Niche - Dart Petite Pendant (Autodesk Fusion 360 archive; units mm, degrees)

design "Dart Petite" references "PCB Single Pendant Canopy"
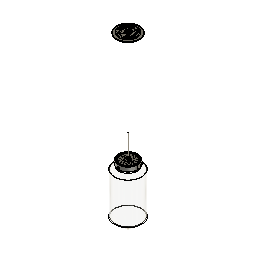
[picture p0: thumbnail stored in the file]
base_feature "Base Feature" bodies "Glass-Dart Petite"
external_derived "ExternalDerived1" bodies "Set Screw", "Strain Relief", "Lead-1", "Lead-2", "Lead-2.1", "Lead-1.1", "Coax", "Stem"
move "Move1"
move "Move2"
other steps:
derived_base_feature "Derived Base Feature" bodies "Set Screw", "Strain Relief", "Lead-1", "Lead-2", "Lead-2.1", "Lead-1.1", "Coax", "Stem"
create_component "CreateComponent1"
named bodies: "Glass-Dart Petite", "Set Screw", "Strain Relief", "Lead-1", "Lead-2", "Lead-2.1", "Lead-1.1", "Coax", "Stem", "Strain Relief Cap", "Nylon Gripper (2)", "Cap", "Thumbscrew (1)", "Thumbscrew (2)", "Thumbscrew (3)", "Niche-PCB", "FJ-Plug Cover", "FJ-Plug", "FJ-Plug1.1", "FJ-Plug1.2", "FJ-Plug1.3", "Fj-Plug1.4", "Canopy", "FJ-Port", "FJ-Port1.1", "Spacer", "Universal Mount", "FJ-Port Cover", "Diffuser"

design "FJ Plug - PCB-Hardware"
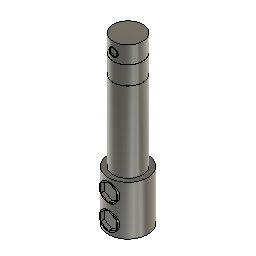
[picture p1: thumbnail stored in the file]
sketch "Sketch1" plane through (0, 0, 0) normal (0, 0, 1) x axis (1, 0, 0)
  circle C1 centre (0, 0) radius 3.048
  point P1 (0, 0)
  point P2 (0, 0)
  coincident P1 P2
  dimension "d1" diameter C1 = 6.096
extrude "Extrude1" new body sketch "Sketch1" along normal blind 34.036
sketch "Sketch2" plane through (0, 0, 0) normal (0, 0, 1) x axis (1, 0, 0)
  circle C1 centre (0, 0) radius 4.064
  point P1 (0, 0)
  point P2 (0, 0)
  coincident P1 P2
  dimension "d4" diameter C1 = 8.128
extrude "Extrude2" add sketch "Sketch2" along normal blind 10.16
sketch "Sketch3" plane through (0, 0, 0) normal (0, 1, 0) x axis (1, 0, 0)
  line L1 (6.35, 0) -> (-6.35, 0)
  line L2 (6.35, -30.48) -> (-6.35, -30.48)
  line L3 (2.54, -30.48) -> (6.35, -30.48)
  line L4 (2.54, -26.67) -> (2.54, -30.48)
  line L5 (6.35, -26.67) -> (2.54, -26.67)
  line L6 (6.35, -30.48) -> (6.35, -26.67)
  horizontal L1
  horizontal L3
  vertical L4
  horizontal L5
  vertical L6
  dimension "d7" = 30.48
revolve "Revolve1" sketch "Sketch3" AlongAngle 360
sketch "Sketch4" plane through (0, 0, 0) normal (0, 1, 0) x axis (1, 0, 0)
  line L1 (2.54, -30.48) -> (3.048, -30.48)
  line L2 (2.54, -26.67) -> (2.54, -30.48)
  line L3 (3.048, -26.67) -> (2.54, -26.67)
  line L4 (3.048, -30.48) -> (3.048, -26.67)
  horizontal L1
  vertical L2
  horizontal L3
  vertical L4
revolve "Revolve2" sketch "Sketch4" AlongAngle 360
chamfer "Chamfer1" distance 0.0254
chamfer "Chamfer2" distance 0.0254
hole "Hole1" HoleDepth 33.401 HoleDiameter 4.826 TipAngle 180
hole "Hole2" HoleDepth 3.81 HoleDiameter 1.778 TipAngle 180
hole "Hole3" HoleDepth 3.81 HoleDiameter 3.81 TipAngle 180
hole "Hole4" HoleDepth 3.81 HoleDiameter 3.81 TipAngle 180
sketch "Sketch5" plane through (0, 0, 0) normal (0, 1, 0) x axis (1, 0, 0)
  circle C1 centre (0, -32.0802) radius 0.889
  dimension "d24" diameter C1 = 1.778
extrude "Extrude3" new body sketch "Sketch5" along normal blind 1.778
move "Move1"
sketch "Sketch6" plane through (0, -3.048, 0) normal (0, -1, 0) x axis (1, 0, 0)
  line L1 (0.7259, 31.6611) -> (0, 31.242)
  line L2 (0.7259, 32.4993) -> (0.7259, 31.6611)
  line L3 (0, 32.9184) -> (0.7259, 32.4993)
  line L4 (-0.7259, 32.4993) -> (0, 32.9184)
  line L5 (-0.7259, 31.6611) -> (-0.7259, 32.4993)
  line L6 (0, 31.242) -> (-0.7259, 31.6611)
  circle C1 centre (0, 32.0802) radius 0.889
  point P2 (0, 32.0802)
  point P9 (0, 32.0802)
  coincident P2 P9
extrude "Extrude4" cut sketch "Sketch6" profile of L1 L2 L3 L4 L5 L6 against normal blind 0.254
sketch "Sketch7" plane through (0, 0, 0) normal (0, 1, 0) x axis (1, 0, 0)
  circle C1 centre (0, -2.4384) radius 1.905
  circle C2 centre (0, -7.5565) radius 1.905
  dimension "d29" diameter C1 = 3.81
  dimension "d30" diameter C2 = 3.81
extrude "Extrude5" new body sketch "Sketch7" profile of C2 along normal blind 3.81
move "Move2"
sketch "Sketch8" plane through (0, -4.064, 0) normal (0, -1, 0) x axis (1, 0, 0)
  line L1 (1.5948, 6.6357) -> (0, 5.715)
  line L2 (1.5948, 8.4772) -> (1.5948, 6.6357)
  line L3 (0, 9.398) -> (1.5948, 8.4772)
  line L4 (-1.5948, 8.4772) -> (0, 9.398)
  line L5 (-1.5948, 6.6357) -> (-1.5948, 8.4772)
  line L6 (0, 5.715) -> (-1.5948, 6.6357)
  circle C1 centre (0, 7.5565) radius 1.905
  point P2 (0, 7.5565)
  point P9 (0, 7.5565)
  coincident P2 P9
extrude "Extrude6" cut sketch "Sketch8" profile of L1 L2 L3 L4 L5 L6 against normal blind 0.762
copy_paste_bodies "CopyPasteBodies2"
move "Move4"
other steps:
base_feature "Base Feature"

design "Flask Petite"
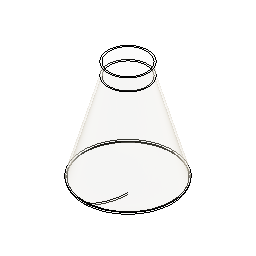
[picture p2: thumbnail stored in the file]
sketch "Sketch1" plane through (0, 0, 0) normal (1, 0, 0) x axis (0, 1, 0)
canvas "Canvas1"
sketch "Sketch2" plane through (0, 0, 0) normal (1, 0, 0) x axis (0, 1, 0)
  line L1 (-5.314, 187.093) -> (-57.384, 187.093)
  line L2 (-57.384, 155.343) -> (-57.384, 187.093)
  line L3 (-121.92, -71.12) -> (-57.384, 155.343)
  line L4 (-5.314, -112.5919) -> (-5.314, 187.093)
  curve K1 (-5.314, -112.5919) -> (-121.92, -74.8854)
  arc A1 centre (-115.3135, -73.0027) radius 6.8695 clockwise from (-121.92, -74.8854) to (-121.92, -71.12)
  point P2 (-57.384, 187.093)
  point P3 (-5.314, 187.093)
  point P4 (-57.384, 155.343)
  horizontal L1
  perpendicular L1 L2
  tangent L3 A1
  perpendicular L1 L4
  dimension "d1" distance P2 P3 = 52.07
  dimension "d2" distance P2 P4 = 31.75
revolve "Revolve1" sketch "Sketch2" AlongAngle 360
fillet "Fillet1" radius 5.08
shell "Shell1" innerThickness 4

design "PCB Single Pendant Canopy" references "PCB Canopy", "Flask Petite", "FJ Cover - PCB-Hardware", "PCB Cap", "Diffuser", "FJ Plug - PCB-Hardware"
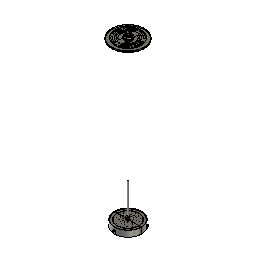
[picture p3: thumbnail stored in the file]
external_derived "ExternalDerived1" bodies "Nylon Gripper", "Set Screw", "Strain Relief", "Lead-1", "Lead-2", "Lead-2.1", "Lead-1.1", "Coax"
external_derived "ExternalDerived2" bodies "FJ-Plug Cover"
move "Move1"
move "Move2" TranslateX 3.175 TranslateY 0.254 TranslateZ 0
move "Move3" TranslateX 0 TranslateY 0 TranslateZ 1092.2
external_derived "ExternalDerived3" bodies "FJ-Plug", "FJ-Plug1.2", "FJ-Plug1.1", "FJ-Plug1.3", "Fj-Plug1.4"
move "Move4" TranslateX 0 TranslateY 0 TranslateZ 1117.6
external_derived "ExternalDerived4" bodies "Nylon Gripper", "Spacer", "Canopy", "FJ-Port", "FJ-Port1.1", "Universal Mount", "FJ-Port Cover", "Lead-1.1"
move "Move5"
move "Move6"
external_derived "ExternalDerived5" bodies "Diffuser"
move "Move7"
external_derived "ExternalDerived6" bodies "Thumbscrew (1)"
align "Align1"
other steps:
derived_base_feature "Derived Base Feature1"
derived_base_feature "Derived Base Feature2" bodies "FJ-Plug Cover"
derived_base_feature "Derived Base Feature3" bodies "FJ-Plug", "FJ-Plug1.1", "FJ-Plug1.2"
derived_base_feature "Derived Base Feature4" bodies "Body1 (1)", "Body1 (1) (1)", "Body2 (1)", "Body1 (2)", "Body1 (3)", "Body1 (4)", "Canopy", "FJ-Port"
derived_base_feature "Derived Base Feature5" bodies "Diffuser"
derived_base_feature "Derived Base Feature6" bodies "Body1", "Thumbscrew (1)"
named bodies: "Nylon Gripper", "Set Screw", "Strain Relief", "Lead-1", "Lead-2", "Lead-2.1", "Lead-1.1", "Coax", "Stem", "stem (2)", "Strain Relief Cap", "Nylon Gripper (2)", "Cap", "Thumbscrew (1)", "Thumbscrew (2)", "Thumbscrew (3)", "Niche-PCB", "FJ-Plug Cover", "FJ-Plug", "FJ-Plug1.1", "FJ-Plug1.2", "FJ-Plug1.3", "Fj-Plug1.4", "Body1 (1)", "Body1 (1) (1)", "Body2 (1)", "Body1 (2)", "Body1 (3)", "Body1 (4)", "Canopy", "FJ-Port", "FJ-Port1.1", "Spacer", "Universal Mount", "FJ-Port Cover", "Diffuser", "Body1"

design "FJ Female"
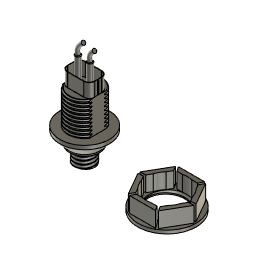
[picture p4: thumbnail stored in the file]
sketch "Sketch1" plane through (0, 0, 0) normal (0, 0, 1) x axis (1, 0, 0)
  circle C1 centre (0, 0) radius 4.445
  point P1 (0, 0)
  point P2 (0, 0)
  coincident P1 P2
  dimension "d1" diameter C1 = 8.89
extrude "Extrude1" new body sketch "Sketch1" along normal blind 6.858
sketch "Sketch2" plane through (0, 0, 6.858) normal (0, 0, 1) x axis (-1, 0, 0)
  circle C1 centre (0, 0) radius 4.445
  circle C2 centre (0, 0) radius 6.985
  point P1 (0, 0)
  point P3 (0, 0)
  coincident P1 P3
  dimension "d4" diameter C2 = 13.97
extrude "Extrude2" add sketch "Sketch2" along normal blind 1.27
work_plane "WorkPlane1" AlongDistance 5.08
sketch "Sketch3" plane through (0, 0, 13.208) normal (0, 0, 1) x axis (1, 0, 0)
  circle C1 centre (0, 0) radius 11.43
  point P1 (0, 0)
  point P2 (0, 0)
  coincident P1 P2
  dimension "d8" diameter C1 = 22.86
loft "Loft1" sketch "Sketch3"
extrude "Extrude3" add of existing geometry blind 1.778
sketch "Sketch4" plane through (0, 0, 14.986) normal (0, 0, 1) x axis (-1, 0, 0)
  circle C1 centre (0, 0) radius 11.43
  circle C2 centre (0, 0) radius 7.62
  point P1 (0, 0)
  point P3 (0, 0)
  coincident P1 P3
  dimension "d11" diameter C2 = 15.24
extrude "Extrude4" add sketch "Sketch4" profile of C2 along normal blind 15.24
sketch "Sketch5" plane through (0, 0, 30.226) normal (0, 0, 1) x axis (-1, 0, 0)
  line L1 (6.35, 0) -> (0, 0)
  line L2 (-6.35, 0) -> (0, 0)
  line L3 (6.35, -4.2121) -> (6.35, 0)
  line L4 (6.35, 4.2121) -> (6.35, 0)
  line L5 (-6.35, -4.2121) -> (-6.35, 0)
  line L6 (-6.35, 4.2121) -> (-6.35, 0)
  circle C1 centre (0, 0) radius 7.62
  point P2 (0, 0)
  point P3 (0, 0)
  point P5 (0, 0)
  point P7 (6.35, -4.2121)
  point P8 (6.35, 4.2121)
  point P9 (-6.35, -4.2121)
  point P10 (-6.35, 0)
  point P11 (-6.35, 4.2121)
  point P4 (6.35, 0)
  point P6 (-6.35, 0)
  coincident P2 P3
  horizontal L1
  coincident P2 P5
  parallel L1 L2
  coincident C1 P7
  perpendicular L1 L3
  coincident C1 P8
  perpendicular L1 L4
  coincident C1 P9
  perpendicular L2 L5
  coincident L2 P10
  perpendicular L2 L6
  coincident C1 P11
  dimension "d14" distance P3 P4 = 6.35
  dimension "d15" distance P5 P6 = 6.35
extrude "Extrude5" cut sketch "Sketch5" profile of C1 L3 L4 L5 L6 against normal blind 15.24
sketch "Sketch6" plane through (0, 0, 30.226) normal (0, 0, 1) x axis (-1, 0, 0)
  line L1 (-6.35, -4.2121) -> (-6.35, 4.2121)
  line L2 (6.35, 4.2121) -> (6.35, -4.2121)
  line L3 (-6.35, -4.2121) -> (6.35, -4.2121)
  line L4 (6.35, 4.2121) -> (-6.35, 4.2121)
  line L5 (6.35, -4.2121) -> (6.35, 4.2121)
  line L6 (-6.35, 4.2121) -> (-6.35, -4.2121)
  line L7 (-6.223, 4.064) -> (6.223, 4.064)
  line L8 (-6.223, -4.064) -> (-6.223, 4.064)
  line L9 (6.223, -4.064) -> (-6.223, -4.064)
  line L10 (6.223, 4.064) -> (6.223, -4.064)
  line L11 (-6.223, -4.064) -> (6.223, 4.064)
  line L12 (6.223, -4.064) -> (-6.223, 4.064)
  arc A1 centre (0, 0) radius 7.62 clockwise from (6.35, -4.2121) to (-6.35, -4.2121)
  arc A2 centre (0, 0) radius 7.62 clockwise from (-6.35, 4.2121) to (6.35, 4.2121)
  point P4 (6.35, -4.2121)
  point P7 (6.35, -4.2121)
  point P3 (-6.35, -4.2121)
  point P8 (-6.35, -4.2121)
  point P2 (-6.35, 4.2121)
  point P9 (-6.35, 4.2121)
  point P6 (6.35, 4.2121)
  point P10 (6.35, 4.2121)
  point P15 (0, 0)
  point P5 (0, 0)
  point P13 (-6.223, -4.064)
  point P14 (6.223, -4.064)
  point P12 (-6.223, 4.064)
  coincident P4 P7
  coincident P3 P8
  coincident P2 P9
  coincident P6 P10
  perpendicular L7 L8
  parallel L7 L9
  parallel L8 L10
  horizontal L7
  coincident L11 P15
  coincident L12 P15
  coincident P5 P15
  dimension "d18" distance P13 P14 = 12.446
  dimension "d19" distance P12 P13 = 8.128
extrude "Extrude6" add sketch "Sketch6" profile of L1 L2 L3 L4 L5 L6 L7 L8 L9 L10 along normal blind 6.35
fillet "Fillet1" radius 2.54
sketch "Sketch7" plane through (6.35, 0, 0) normal (1, 0, 0) x axis (0, 1, 0)
  line L1 (1.6721, 36.576) -> (1.6721, 30.226)
  line L2 (-1.6721, 36.576) -> (1.6721, 36.576)
  line L3 (-1.6721, 30.226) -> (-1.6721, 36.576)
  line L4 (-4.2121, 30.226) -> (-1.6721, 30.226)
  line L5 (-4.2121, 14.986) -> (-4.2121, 30.226)
  line L6 (4.2121, 14.986) -> (-4.2121, 14.986)
  line L7 (4.2121, 30.226) -> (4.2121, 14.986)
  line L8 (1.6721, 30.226) -> (4.2121, 30.226)
  line L9 (0.254, 36.576) -> (-0.2492, 36.576)
  line L10 (0.254, 30.226) -> (0.254, 36.576)
  line L11 (-0.2492, 30.226) -> (0.254, 30.226)
  line L12 (-0.2492, 36.576) -> (-0.2492, 30.226)
  point P10 (-0.2492, 36.576)
  horizontal L9
  vertical L10
  horizontal L11
  vertical L12
  coincident L2 P10
extrude "Extrude7" cut sketch "Sketch7" profile of L2 L9 L10 L11 L12 against normal blind 0.508
thread "Thread1"
fillet "Fillet2" radius 0.635
thread "Thread2"
sketch "Sketch8" plane through (0, 0, 30.226) normal (0, 0, 1) x axis (-1, 0, 0)
  line L1 (-6.223, -1.524) -> (-6.223, -0.254)
  line L2 (3.683, -4.064) -> (-3.683, -4.064)
  line L3 (6.223, 1.524) -> (6.223, -1.524)
  line L4 (-3.683, 4.064) -> (3.683, 4.064)
  line L5 (-6.223, 0.2492) -> (-6.223, 1.524)
  line L6 (-6.35, 0.2492) -> (-6.223, 0.2492)
  line L7 (-6.35, -0.254) -> (-6.35, 0.2492)
  line L8 (-6.223, -0.254) -> (-6.35, -0.254)
  arc A1 centre (-3.683, -1.524) radius 2.54 clockwise from (-3.683, -4.064) to (-6.223, -1.524)
  arc A2 centre (3.683, -1.524) radius 2.54 clockwise from (6.223, -1.524) to (3.683, -4.064)
  arc A3 centre (3.683, 1.524) radius 2.54 clockwise from (3.683, 4.064) to (6.223, 1.524)
  arc A4 centre (-3.683, 1.524) radius 2.54 clockwise from (-6.223, 1.524) to (-3.683, 4.064)
  circle C1 centre (3.048, 0) radius 1.27
  circle C2 centre (-2.54, 0) radius 1.27
  dimension "d26" diameter C1 = 2.54
  dimension "d27" diameter C2 = 2.54
extrude "Extrude8" add sketch "Sketch8" profile of C1 C2 along normal blind 11.43
sketch "Sketch9" plane through (0, 0, 0) normal (0, 1, 0) x axis (1, 0, 0)
  curve K1 (4.572, -46.99) -> (2.54, -41.656)
  curve K2 (-0.508, -47.752) -> (-3.048, -41.656)
pipe "Pipe1" SectionSize 1.778 SectionThickness 0.0762
pipe "Pipe2" SectionSize 1.778 SectionThickness 0.0762
sketch "Sketch10" plane through (0, 0, 0) normal (0, 0, 1) x axis (1, 0, 0)
  circle C1 centre (38.1, 0) radius 13.462
  dimension "d38" diameter C1 = 26.924
extrude "Extrude9" new body sketch "Sketch10" along normal blind 1.524
sketch "Sketch11" plane through (0, 0, 1.524) normal (0, 0, 1) x axis (-1, 0, 0)
  circle C1 centre (-38.1, 0) radius 13.462
  circle C2 centre (-38.1, 0) radius 9.271
  concentric C1 C2
  dimension "d41" diameter C2 = 18.542
extrude "Extrude10" cut sketch "Sketch11" profile of C2 against normal blind 7.62
sketch "Sketch12" plane through (0, 0, 1.524) normal (0, 0, 1) x axis (-1, 0, 0)
  line L1 (-24.9018, 0) -> (-31.5009, -11.43)
  line L2 (-31.5009, 11.43) -> (-24.9018, 0)
  line L3 (-44.6991, 11.43) -> (-31.5009, 11.43)
  line L4 (-51.2982, 0) -> (-44.6991, 11.43)
  line L5 (-44.6991, -11.43) -> (-51.2982, 0)
  line L6 (-31.5009, -11.43) -> (-44.6991, -11.43)
  line L7 (-27.3948, 0) -> (-32.7474, -9.271)
  line L8 (-32.7474, 9.271) -> (-27.3948, 0)
  line L9 (-43.4526, 9.271) -> (-32.7474, 9.271)
  line L10 (-48.8052, 0) -> (-43.4526, 9.271)
  line L11 (-43.4526, -9.271) -> (-48.8052, 0)
  line L12 (-32.7474, -9.271) -> (-43.4526, -9.271)
  circle C1 centre (-38.1, 0) radius 9.271
  circle C2 centre (-38.1, 0) radius 13.462
  point P2 (-38.1, 0)
  point P9 (-38.1, 0)
  point P16 (-38.1, 0)
  coincident P2 P9
  coincident P9 P16
extrude "Extrude11" add sketch "Sketch12" profile of L1 L2 L3 L4 L5 L6 L7 L8 L9 L10 L11 L12 along normal blind 7.112
thread "Thread3"
sketch "Sketch13" plane through (0, 0, 8.636) normal (0, 0, 1) x axis (-1, 0, 0)
  line L1 (-43.4526, -9.271) -> (-32.7474, -9.271)
  line L2 (-48.8052, 0) -> (-43.4526, -9.271)
  line L3 (-43.4526, 9.271) -> (-48.8052, 0)
  line L4 (-32.7474, 9.271) -> (-43.4526, 9.271)
  line L5 (-27.3948, 0) -> (-32.7474, 9.271)
  line L6 (-32.7474, -9.271) -> (-27.3948, 0)
  line L7 (-31.5009, -11.43) -> (-44.6991, -11.43)
  line L8 (-24.9018, 0) -> (-31.5009, -11.43)
  line L9 (-31.5009, 11.43) -> (-24.9018, 0)
  line L10 (-44.6991, 11.43) -> (-31.5009, 11.43)
  line L11 (-51.2982, 0) -> (-44.6991, 11.43)
  line L12 (-44.6991, -11.43) -> (-51.2982, 0)
sketch "Sketch14" plane through (0, 0, 8.636) normal (0, 0, 1) x axis (-1, 0, 0)
  circle C1 centre (-38.1, 0) radius 9.525
  dimension "d46" diameter C1 = 19.05
extrude "Extrude12" cut sketch "Sketch14" against normal blind 7.112
sketch "Sketch15" plane through (0, 0, 8.636) normal (0, 0, 1) x axis (-1, 0, 0)
  line L1 (-51.2982, 0) -> (-44.6991, 11.43)
  line L2 (-43.4526, 9.271) -> (-48.8052, 0)
  line L3 (-32.7474, 9.271) -> (-43.4526, 9.271)
  line L4 (-44.6991, 11.43) -> (-31.5009, 11.43)
  line L5 (-44.1911, 11.43) -> (-42.7995, 9.271)
  line L6 (-40.2139, 9.271) -> (-42.7995, 9.271)
  line L7 (-43.7181, 8.8112) -> (-45.0232, 10.8687)
  line L8 (-43.4526, 9.271) -> (-42.7995, 9.271)
  line L9 (-43.7181, 8.8112) -> (-43.4526, 9.271)
  line L10 (-45.0232, 10.8687) -> (-44.6991, 11.43)
  line L11 (-44.1911, 11.43) -> (-44.6991, 11.43)
  line L12 (-48.5398, -0.4598) -> (-50.9742, -0.5613)
  line L13 (-48.5398, -0.4598) -> (-48.8052, 0)
  line L14 (-48.8052, 0) -> (-48.4787, 0.5657)
  line L15 (-51.0442, 0.4399) -> (-48.4787, 0.5657)
  line L16 (-51.0442, 0.4399) -> (-51.2982, 0)
  line L17 (-50.9742, -0.5613) -> (-51.2982, 0)
  line L18 (-42.9217, -9.271) -> (-44.051, -11.43)
  line L19 (-42.9217, -9.271) -> (-43.4526, -9.271)
  line L20 (-43.4526, -9.271) -> (-43.7792, -8.7053)
  line L21 (-44.9531, -10.9901) -> (-43.7792, -8.7053)
  line L22 (-44.9531, -10.9901) -> (-44.6991, -11.43)
  line L23 (-44.051, -11.43) -> (-44.6991, -11.43)
  line L24 (-32.4819, -8.8112) -> (-31.1768, -10.8687)
  line L25 (-32.4819, -8.8112) -> (-32.7474, -9.271)
  line L26 (-32.7474, -9.271) -> (-33.4005, -9.271)
  line L27 (-32.0089, -11.43) -> (-33.4005, -9.271)
  line L28 (-32.0089, -11.43) -> (-31.5009, -11.43)
  line L29 (-31.1768, -10.8687) -> (-31.5009, -11.43)
  line L30 (-27.6603, 0.4598) -> (-25.2258, 0.5613)
  line L31 (-27.6603, 0.4598) -> (-27.3948, 0)
  line L32 (-27.3948, 0) -> (-27.7214, -0.5657)
  line L33 (-25.1558, -0.4399) -> (-27.7214, -0.5657)
  line L34 (-25.1558, -0.4399) -> (-24.9018, 0)
  line L35 (-25.2258, 0.5613) -> (-24.9018, 0)
  line L36 (-33.2783, 9.271) -> (-32.149, 11.43)
  line L37 (-33.2783, 9.271) -> (-32.7474, 9.271)
  line L38 (-32.7474, 9.271) -> (-32.4208, 8.7053)
  line L39 (-31.2469, 10.9901) -> (-32.4208, 8.7053)
  line L40 (-31.2469, 10.9901) -> (-31.5009, 11.43)
  line L41 (-32.149, 11.43) -> (-31.5009, 11.43)
  point P10 (-42.7995, 9.271)
  point P12 (-45.0232, 10.8687)
  point P13 (-43.7181, 8.8112)
  point P5 (-43.4526, 9.271)
  point P14 (-43.4526, 9.271)
  point P16 (-44.1911, 11.43)
  point P9 (-44.6991, 11.43)
  point P15 (-44.6991, 11.43)
  horizontal L6
  coincident L3 P10
  coincident L1 P12
  coincident L2 P13
  coincident P5 P14
  coincident L4 P16
  coincident P9 P15
  coincident L4 P16
  dimension "d50" distance P15 P16 = 0.508
  dimension "d54" C-Pattern1-Angle = 360
extrude "Extrude13" cut sketch "Sketch15" profile of L1 L2 L3 L4 L5 L7 L8 L9 L10 L11 L12 L13 L14 L15 L16 L17 L18 L19 L20 L21 L22 L23 L24 L25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 against normal blind 7.112

design "FJ Cover - PCB-Hardware"
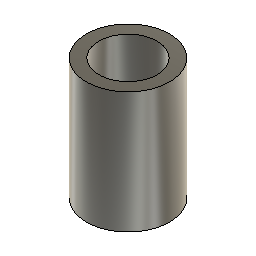
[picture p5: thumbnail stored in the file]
sketch "Sketch1" plane through (0, 0, 0) normal (0, 0, 1) x axis (1, 0, 0)
  circle C1 centre (0, 0) radius 6.35
  point P1 (0, 0)
  point P2 (0, 0)
  coincident P1 P2
  dimension "d1" diameter C1 = 12.7
extrude "Extrude1" new body sketch "Sketch1" along normal blind 18.542
hole "Hole1" HoleDepth 13.97 HoleDiameter 8.89 TipAngle 180
hole "Hole2" HoleDepth 13.97 HoleDiameter 3.556 TipAngle 180

design "PCB Canopy" references "Canopy - PCB-Hardware", "Port Cover - PCB-Hardware", "Universal Mounting Bracket - PCB-Hardware", "Spacer - PCB-Hardware", "FJ Female", "FJ Cover - PCB-Hardware"
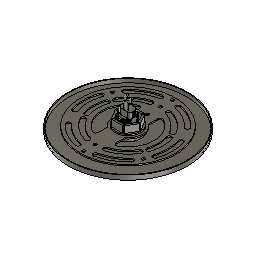
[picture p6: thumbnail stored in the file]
external_derived "ExternalDerived"
external_derived "ExternalDerived"
external_derived "ExternalDerived3" bodies "Body1 (1)"
external_derived "ExternalDerived4"
external_derived "ExternalDerived5"
move "Move1"
move "Move2"
move "Move3"
move "Move4"
move "Move5"
move "Move6"
move "Move7"
move "Move8"
external_derived "ExternalDerived6"
align "Align1"
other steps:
derived_base_feature "Derived Base Feature" bodies "Body1"
derived_base_feature "Derived Base Feature" bodies "Body1 (1)", "Body2"
derived_base_feature "Derived Base Feature3" bodies "Body1 (2)", "Body1 (1)"
derived_base_feature "Derived Base Feature4" bodies "Body1 (3)"
derived_base_feature "Derived Base Feature5" bodies "Body1 (4)"
derived_base_feature "Derived Base Feature6" bodies "Body1 (5)"
named bodies: "Body1", "Body1 (1)", "Body2", "Body1 (2)", "Body1 (3)", "Body1 (4)", "Body1 (5)"

design "Spacer - PCB-Hardware"
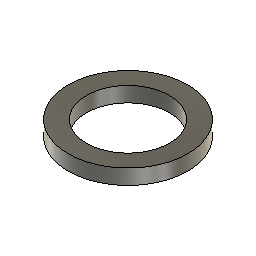
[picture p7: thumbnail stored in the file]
sketch "Sketch1" plane through (0, 0, 0) normal (0, 0, 1) x axis (1, 0, 0)
  circle C1 centre (0, 0) radius 14.097
  circle C2 centre (0, 0) radius 9.779
  point P1 (0, 0)
  point P2 (0, 0)
  point P3 (0, 0)
  coincident P1 P2
  coincident P1 P3
  dimension "d1" diameter C1 = 28.194
  dimension "d2" diameter C2 = 19.558
extrude "Extrude1" new body sketch "Sketch1" along normal blind 3.556

design "Universal Mounting Bracket - PCB-Hardware"
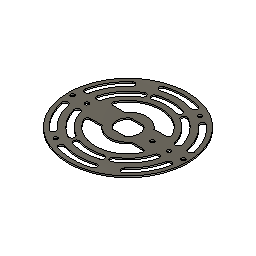
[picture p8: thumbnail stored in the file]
sketch "Sketch1" plane through (0, 0, 0) normal (0, 0, 1) x axis (1, 0, 0)
  circle C1 centre (0, 0) radius 50.8
  arc A1 centre (0, 0) radius 42.545 clockwise from (-13.1471, 40.4627) to (13.1471, 40.4627)
  arc A2 centre (0, 0) radius 47.371 clockwise from (-14.6384, 45.0525) to (14.6384, 45.0525)
  arc A3 centre (-13.8928, 42.7576) radius 2.413 clockwise from (-13.1471, 40.4627) to (-14.6384, 45.0525)
  arc A4 centre (13.8928, 42.7576) radius 2.413 clockwise from (14.6384, 45.0525) to (13.1471, 40.4627)
  arc A5 centre (0, 0) radius 47.371 clockwise from (-46.3358, 9.849) to (-31.6974, 35.2035)
  arc A6 centre (0, 0) radius 42.545 clockwise from (-41.6153, 8.8456) to (-28.4682, 31.6171)
  arc A7 centre (-43.9756, 9.3473) radius 2.413 clockwise from (-41.6153, 8.8456) to (-46.3358, 9.849)
  arc A8 centre (-30.0828, 33.4103) radius 2.413 clockwise from (-31.6974, 35.2035) to (-28.4682, 31.6171)
  arc A9 centre (0, 0) radius 47.371 clockwise from (-31.6974, -35.2035) to (-46.3358, -9.849)
  arc A10 centre (0, 0) radius 42.545 clockwise from (-28.4682, -31.6171) to (-41.6153, -8.8456)
  arc A11 centre (-30.0828, -33.4103) radius 2.413 clockwise from (-28.4682, -31.6171) to (-31.6974, -35.2035)
  arc A12 centre (-43.9756, -9.3473) radius 2.413 clockwise from (-46.3358, -9.849) to (-41.6153, -8.8456)
  arc A13 centre (0, 0) radius 47.371 clockwise from (14.6384, -45.0525) to (-14.6384, -45.0525)
  arc A14 centre (0, 0) radius 42.545 clockwise from (13.1471, -40.4627) to (-13.1471, -40.4627)
  arc A15 centre (13.8928, -42.7576) radius 2.413 clockwise from (13.1471, -40.4627) to (14.6384, -45.0525)
  arc A16 centre (-13.8928, -42.7576) radius 2.413 clockwise from (-14.6384, -45.0525) to (-13.1471, -40.4627)
  arc A17 centre (0, 0) radius 47.371 clockwise from (46.3358, -9.849) to (31.6974, -35.2035)
  arc A18 centre (0, 0) radius 42.545 clockwise from (41.6153, -8.8456) to (28.4682, -31.6171)
  arc A19 centre (43.9756, -9.3473) radius 2.413 clockwise from (41.6153, -8.8456) to (46.3358, -9.849)
  arc A20 centre (30.0828, -33.4103) radius 2.413 clockwise from (31.6974, -35.2035) to (28.4682, -31.6171)
  arc A21 centre (0, 0) radius 47.371 clockwise from (31.6974, 35.2035) to (46.3358, 9.849)
  arc A22 centre (0, 0) radius 42.545 clockwise from (28.4682, 31.6171) to (41.6153, 8.8456)
  arc A23 centre (30.0828, 33.4103) radius 2.413 clockwise from (28.4682, 31.6171) to (31.6974, 35.2035)
  arc A24 centre (43.9756, 9.3473) radius 2.413 clockwise from (46.3358, 9.849) to (41.6153, 8.8456)
  arc A25 centre (0, 0) radius 32.385 clockwise from (-31.2224, 8.5995) to (-16.1925, 28.0462)
  arc A26 centre (0, 0) radius 37.338 clockwise from (-35.9514, 10.0809) to (-18.669, 32.3357)
  arc A27 centre (0, 0) radius 32.385 clockwise from (16.1925, 28.0462) to (31.2224, 8.5995)
  arc A28 centre (0, 0) radius 32.385 clockwise from (-10.0075, 30.8) to (10.0075, 30.8)
  arc A29 centre (0, 0) radius 37.338 clockwise from (18.669, 32.3357) to (35.9514, 10.0809)
  arc A30 centre (0, 0) radius 37.338 clockwise from (-11.5381, 35.5105) to (11.5381, 35.5105)
  arc A31 centre (-33.5467, 9.4685) radius 2.4814 clockwise from (-31.1111, 8.9939) to (-35.9167, 10.2037)
  arc A32 centre (-17.4307, 30.1909) radius 2.4765 clockwise from (-18.669, 32.3357) to (-16.1925, 28.0462)
  arc A33 centre (-10.7728, 33.1553) radius 2.4765 clockwise from (-10.0075, 30.8) to (-11.5381, 35.5105)
  arc A34 centre (10.7728, 33.1553) radius 2.4765 clockwise from (11.5381, 35.5105) to (10.0075, 30.8)
  arc A35 centre (17.4307, 30.1909) radius 2.4765 clockwise from (16.1925, 28.0462) to (18.669, 32.3357)
  arc A36 centre (33.5467, 9.4685) radius 2.4814 clockwise from (35.9167, 10.2037) to (31.1111, 8.9939)
  arc A37 centre (-33.5467, -9.4685) radius 2.4814 clockwise from (-35.9167, -10.2037) to (-31.1111, -8.9939)
  arc A38 centre (0, 0) radius 37.338 clockwise from (-18.669, -32.3357) to (-35.9514, -10.0809)
  arc A39 centre (0, 0) radius 32.385 clockwise from (-16.1925, -28.0462) to (-31.2224, -8.5995)
  arc A40 centre (-17.4307, -30.1909) radius 2.4765 clockwise from (-16.1925, -28.0462) to (-18.669, -32.3357)
  arc A41 centre (-10.7728, -33.1553) radius 2.4765 clockwise from (-11.5381, -35.5105) to (-10.0075, -30.8)
  arc A42 centre (0, 0) radius 37.338 clockwise from (11.5381, -35.5105) to (-11.5381, -35.5105)
  arc A43 centre (0, 0) radius 32.385 clockwise from (10.0075, -30.8) to (-10.0075, -30.8)
  arc A44 centre (10.7728, -33.1553) radius 2.4765 clockwise from (10.0075, -30.8) to (11.5381, -35.5105)
  arc A45 centre (17.4307, -30.1909) radius 2.4765 clockwise from (18.669, -32.3357) to (16.1925, -28.0462)
  arc A46 centre (0, 0) radius 37.338 clockwise from (35.9514, -10.0809) to (18.669, -32.3357)
  arc A47 centre (0, 0) radius 32.385 clockwise from (31.2224, -8.5995) to (16.1925, -28.0462)
  arc A48 centre (33.5467, -9.4685) radius 2.4814 clockwise from (31.1111, -8.9939) to (35.9167, -10.2037)
  point P1 (0, 0)
  point P2 (0, 0)
  point P71 (-35.9514, 10.0809)
  point P72 (-31.2224, 8.5995)
  point P73 (35.9514, 10.0809)
  point P74 (31.2224, 8.5995)
  point P75 (-31.1111, 8.9939)
  point P76 (-35.9167, 10.2037)
  point P77 (35.9167, 10.2037)
  point P78 (31.1111, 8.9939)
  coincident P1 P2
  concentric C1 A2
  concentric A1 A2
  concentric A17 A26
  concentric A25 A26
  concentric A25 A27
  concentric A26 A29
  concentric A27 A28
  concentric A29 A30
  coincident P71 A31
  coincident P72 A31
  coincident P73 A36
  coincident P74 A36
  coincident A25 P75
  coincident A26 P76
  coincident A29 P77
  coincident A27 P78
  dimension "d1" diameter C1 = 101.6
  dimension "d2" diameter A2 = 94.742
  dimension "d11" diameter A26 = 74.676
  dimension "d12" diameter A25 = 64.77
  dimension "d10" C-Pattern1-Angle = 360
sketch "Sketch2" plane through (0, 0, 0) normal (0, 0, 1) x axis (1, 0, 0)
  line L1 (5.3986, -8.001) -> (-5.3986, -8.001)
  line L2 (5.3986, 8.001) -> (-5.3986, 8.001)
  arc A1 centre (0, 0) radius 9.652 clockwise from (-5.3986, -8.001) to (-5.3986, 8.001)
  arc A2 centre (0, 0) radius 9.652 clockwise from (5.3986, 8.001) to (5.3986, -8.001)
  point P1 (0, 0)
  point P2 (0, 0)
  coincident P1 P2
  concentric A1 A2
  dimension "d6" diameter A1 = 19.304
sketch "Sketch3" plane through (0, 0, 0) normal (0, 0, 1) x axis (1, 0, 0)
  line L1 (-12.5409, 9.525) -> (-22.2072, 9.525)
  line L2 (22.2072, 9.525) -> (12.5409, 9.525)
  line L3 (-12.5409, -9.525) -> (-22.2072, -9.525)
  line L4 (22.2072, -9.525) -> (12.5409, -9.525)
  arc A1 centre (0, 0) radius 15.748 clockwise from (12.5409, -9.525) to (-12.5409, -9.525)
  arc A2 centre (0, 0) radius 15.748 clockwise from (-12.5409, 9.525) to (12.5409, 9.525)
  arc A3 centre (0, 0) radius 27.813 clockwise from (24.4391, -13.2776) to (-24.4391, -13.2776)
  arc A4 centre (0, 0) radius 27.813 clockwise from (-24.4391, 13.2776) to (24.4391, 13.2776)
  arc A5 centre (-22.2072, 12.065) radius 2.54 clockwise from (-22.2072, 9.525) to (-24.4391, 13.2776)
  arc A6 centre (22.2072, 12.065) radius 2.54 clockwise from (24.4391, 13.2776) to (22.2072, 9.525)
  arc A7 centre (-22.2072, -12.065) radius 2.54 clockwise from (-24.4391, -13.2776) to (-22.2072, -9.525)
  arc A8 centre (22.2072, -12.065) radius 2.54 clockwise from (22.2072, -9.525) to (24.4391, -13.2776)
  point P1 (0, 0)
  point P2 (0, 0)
  point P5 (12.5409, 9.525)
  coincident P1 P2
  concentric A1 A3
  coincident P5 A1
  collinear L1 L2
  collinear L3 L4
  concentric A1 A2
  concentric A3 A4
  tangent L1 A5
  tangent A4 A5
  tangent L2 A6
  tangent A4 A6
  equal A5 A6
  tangent L3 A7
  tangent A3 A7
  equal A5 A7
  tangent L4 A8
  tangent A3 A8
  equal A5 A8
  dimension "d17" diameter A3 = 55.626
  dimension "d18" diameter A1 = 31.496
  dimension "d37" radius A5 = 2.54
sketch "Sketch4" plane through (0, 0, 0) normal (0, 0, 1) x axis (1, 0, 0)
  circle C1 centre (22.479, 38.9348) radius 1.651
  circle C2 centre (-22.479, -38.9348) radius 1.651
  circle C3 centre (-34.8615, 0) radius 1.651
  circle C4 centre (-47.117, 0) radius 1.651
  circle C5 centre (34.8615, 0) radius 1.651
  circle C6 centre (47.117, 0) radius 1.651
  circle C7 centre (20.701, 0) radius 1.651
  dimension "d36" diameter C7 = 3.302
  dimension "d25" C-Pattern2-Angle = 180
extrude "Extrude1" new body sketch "Sketch1" profile of C1 A2 A1 A3 A4 A5 A6 A7 A8 A9 A10 A11 A12 A13 A14 A15 A16 A17 A18 A19 A20 A21 A22 A23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 along normal blind 1.27
extrude "Extrude2" cut sketch "Sketch3" + "Sketch2" profile of S2:A2 S2:L1 S2:L2 S1:A4 S1:A2 S1:L4 S1:L2 S1:A5 S1:A6 S1:A7 S1:A8 blind 1.27
extrude "Extrude3" cut sketch "Sketch4" along normal blind 1.27

design "Port Cover - PCB-Hardware"
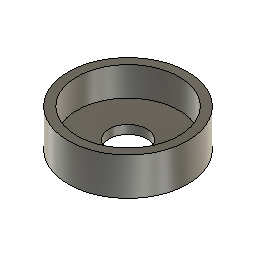
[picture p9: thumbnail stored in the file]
sketch "Sketch1" plane through (0, 0, 0) normal (0, 0, 1) x axis (1, 0, 0)
  circle C1 centre (0, 0) radius 14.097
  point P1 (0, 0)
  point P2 (0, 0)
  coincident P1 P2
  dimension "d1" diameter C1 = 28.194
extrude "Extrude1" new body sketch "Sketch1" along normal blind 8.89
shell "Shell1" innerThickness 2.032
hole "Hole1" HoleDepth 22.86 HoleDiameter 8.89 TipAngle 118

design "PCB Cap"
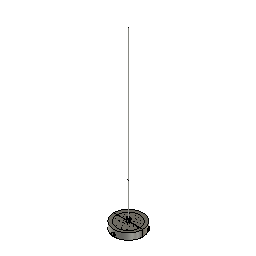
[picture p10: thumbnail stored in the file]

design "Canopy - PCB-Hardware"
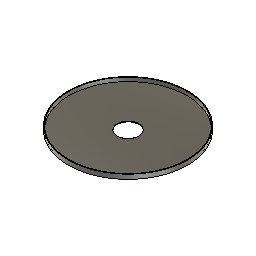
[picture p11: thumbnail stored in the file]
sketch "Sketch1" plane through (0, 0, 0) normal (0, 0, 1) x axis (1, 0, 0)
  circle C1 centre (0, 0) radius 63.5
  point P1 (0, 0)
  point P2 (0, 0)
  coincident P1 P2
extrude "Extrude1" new body sketch "Sketch1" along normal blind 4.826
shell "Shell1" innerThickness 0.762
hole "Hole1" HoleDepth 22.86 HoleDiameter 22.86 TipAngle 118

design "Diffuser"
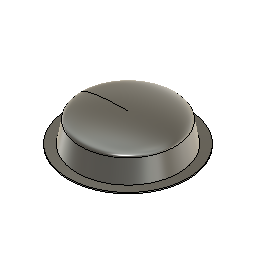
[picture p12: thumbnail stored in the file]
sketch "Sketch1" plane through (0, 0, 0) normal (0, 1, 0) x axis (1, 0, 0)
sketch "Sketch2" plane through (0, 0, 0) normal (0, 0, 1) x axis (1, 0, 0)
  circle C1 centre (0, 0) radius 43.18
  point P1 (0, 0)
  point P2 (0, 0)
  coincident P1 P2
  dimension "d1" diameter C1 = 86.36
sketch "Sketch4" plane through (0, 0, 0) normal (0, 0, 1) x axis (1, 0, 0)
  circle C1 centre (0, 0) radius 50.8
  point P1 (0, 0)
  point P2 (0, 0)
  coincident P1 P2
  dimension "d2" diameter C1 = 101.6
extrude "Extrude1" new body sketch "Sketch4" along normal blind 1.016
sketch "Sketch5" plane through (0, 0, 1.016) normal (0, 0, 1) x axis (-1, 0, 0)
  circle C1 centre (0, 0) radius 50.8
  circle C2 centre (0, 0) radius 42.545
  concentric C1 C2
  dimension "d5" diameter C2 = 85.09
sketch "Sketch8" plane through (0, 0, 1.016) normal (0, 0, 1) x axis (-1, 0, 0)
  circle C1 centre (0, 0) radius 42.545
sketch "Sketch11" plane through (0, 0, 0) normal (0, 1, 0) x axis (1, 0, 0)
sketch "Sketch14" plane through (0, 0, 0) normal (0, 1, 0) x axis (1, 0, 0)
sketch "Sketch15" plane through (0, 0, 1.016) normal (0, 0, 1) x axis (-1, 0, 0)
  line L1 (-42.545, 0) -> (0, 0)
  circle C1 centre (0, 0) radius 42.545
  point P1 (0, 0)
  point P3 (0, 0)
  point P4 (-42.545, 0)
  coincident P1 P3
  coincident C1 P4
  horizontal L1
sketch "Sketch16" plane through (0, 0, 0) normal (0, 0, -1) x axis (1, 0, 0)
  circle C1 centre (0, 0) radius 50.8
sketch "Sketch17" plane through (0, 0, 0) normal (0, 1, 0) x axis (1, 0, 0)
  line L1 (0, -18.8361) -> (40.0012, -18.8361)
  line L2 (0, -1.016) -> (43.18, -1.016)
  line L3 (40.0012, -18.8361) -> (43.18, -1.016)
  line L4 (0, -1.016) -> (0, -25.146)
  line L5 (0, -1.016) -> (43.18, -1.016)
  line L6 (0, -25.1861) -> (0, -1.016)
  curve K1 (0, -25.1861) -> (0, -12.4861)
  curve K2 (40.0012, -18.8361) -> (-40.0012, -18.8361)
  line L7 (0, -12.4861) -> (0, -25.146)
  closed curve K3 centre (0, -18.8361)
  point P3 (0, -1.016)
  point P6 (0, -1.016)
  point P9 (0, -1.016)
  point P10 (0, -1.016)
  point P8 (0, -12.4861)
  point P7 (0, -25.1861)
  point P14 (-40.0012, -18.8361)
  point P11 (40.0012, -18.8361)
  point P4 (43.18, -1.016)
  coincident P3 P6
  coincident P3 P9
  perpendicular L2 L4
  coincident P3 P10
  perpendicular L5 L6
  horizontal L1
  perpendicular L1 K1
  coincident P8 K3
  coincident P7 K3
  coincident K3 P14
  coincident P11 K3
  parallel K1 L7
  dimension "d17" distance P3 P4 = 43.18
revolve "Revolve4" sketch "Sketch17" AlongAngle 360
shell "Shell5" innerThickness 1.016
